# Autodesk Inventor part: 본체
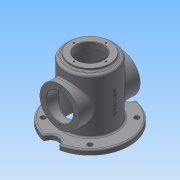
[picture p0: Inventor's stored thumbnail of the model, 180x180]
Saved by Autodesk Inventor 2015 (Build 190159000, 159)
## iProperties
Created: 2018-04
Part Number: 본체
Material: 일반
Document SubType Name: Modeling
Designer: user
Density: 1 g/cm^3
Appearance: 기본값
Mass: 425.882 g
Surface Area: 1203.14 cm^2
Volume: 425.882 cm^3
Author: user
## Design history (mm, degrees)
sketch "스케치2"
  geometry: C1 r 45 at (0, 0); C2 r 50 at (0, 0); 1 further point
  constraints: 2 centre point, 2 coincident
  dimensions: "d0" = 90 diameter of C1; "d1" = 100 diameter of C2
extrude "돌출1" new body sketch "스케치2" distance "d2" = 128; taper "d3" = 0 deg
node "작업 평면1"
sketch "스케치3"
  geometry: L1 (0, 0)-(0, 80); L2 (0, 0)-(0, -80); C1 r 45 at (0, 0); A1 r 15 centre (0, 80) between (-14.934, 78.594) and (14.934, 78.594); A2 r 15 centre (0, -80) between (14.934, -78.594) and (-14.934, -78.594); A3 r 80 centre (0, 0) between (-14.934, 78.594) and (-14.934, -78.594); A4 r 80 centre (0, 0) between (14.934, -78.594) and (14.934, 78.594); A5 r 67.5 centre (0, 0) between (-7.604, 67.07) and (-7.604, -67.07); A6 r 67.5 centre (0, 0) between (7.604, -67.07) and (7.604, 67.07); 1 further point
  constraints: 16 point on circle, 7 centre point, 5 coincident, 4 end point, 2 vertical
  dimensions: "d6" = 90 diameter of C1; "d10" = 30 diameter of A1; "d11" = 30 diameter of A2; "d12" = 80 distance of L1.start L1.end; "d13" = 80 distance of L1.start L2.end; "d14" = 80 radius of A3; "d15" = 67.5 radius of A5; "d16" = 67.5 radius of A6; "d17" = 80 radius of A4
extrude "돌출2" join sketch "스케치3" distance "d18" = 10; taper "d19" = 0 deg
sketch "스케치4"
  geometry: L1 (0, 0)-(-47.73, 47.73); L2 (0, 0)-(-47.73, -47.73); L3 (0, 0)-(0, -36.099); L4 (0, 0)-(47.73, 47.73); L5 (0, 0)-(47.73, -47.73); C1 r 50 at (0, 0) reference; A1 r 67.5 centre (0, 0) between (-47.73, 47.73) and (-47.73, -47.73); 4 further points
  constraints: 10 end point, 5 coincident, 2 point on circle, 2 symmetric about line, 1 centre point, 1 vertical
  dimensions: "d21" = 45 deg angle of L3 L2; "d22" = 90 deg angle of L1 L2; "d23" = 135 diameter of A1
hole "구멍1" sketch "스케치4" at (-47.73, -47.73), (-47.73, 47.73), (47.73, 47.73), (47.73, -47.73) diameter "d24" = 10; stored, may be unused: countersink angle "d28" = 90 deg, drill point angle "d30" = 118 deg; dims "d25" = 6, "d26" = 4, "d27" = 2, "d29" = 8
node "작업 평면2"
sketch "스케치6"
  geometry: C1 r 27 at (0, 0); C2 r 40 at (0, 0); 1 further point
  constraints: 2 centre point, 2 coincident
  dimensions: "d32" = 54 diameter of C1; "d33" = 80 diameter of C2
extrude "돌출3" join sketch "스케치6" distance "d34" = 5; taper "d35" = 0 deg
node "작업 평면3"
sketch "스케치7"
  geometry: C1 r 50 at (0, 0); 1 further point
  constraints: 1 centre point, 1 coincident
  dimensions: "d37" = 100 diameter of C1
extrude "돌출4" join sketch "스케치7" distance "d38" = 8; taper "d39" = 0 deg
extrude "돌출5" cut sketch "스케치6" stored distance "d40" = 8; taper "d41" = 0 deg
node "작업 평면4"
sketch "스케치10"
  geometry: L1 (0, 0)-(0, 68); C1 r 40 at (0, 68); C2 r 27 at (0, 68)
  constraints: 2 centre point, 2 coincident, 2 end point, 1 vertical
  dimensions: "d48" = 68 distance of L1.start L1.end; "d49" = 80 diameter of C1; "d50" = 54 diameter of C2
extrude "돌출6" join sketch "스케치10" stored distance "d51" = 8; taper "d52" = 0 deg
extrude "돌출7" cut sketch "스케치10" stored distance "d53" = 8; taper "d54" = 0 deg
sketch "스케치11"
  geometry: L1 (0, 0)-(0, -32.5); L2 (0, 0)-(32.5, 0); L3 (0, 0)-(-32.5, 0); L4 (0, 0)-(0, 32.5); C1 r 40 at (0, 0) reference; A1 r 32.5 centre (0, 0) between (0, -32.5) and (32.5, 0); 4 further points
  constraints: 8 end point, 5 coincident, 4 point on circle, 2 horizontal, 2 vertical, 1 centre point
  dimensions: "d55" = 65 diameter of A1
hole "구멍2" sketch "스케치11" at (0, -32.5), (-32.5, 0), (0, 32.5), (32.5, 0) diameter "d56" = 3.242; stored, may be unused: countersink angle "d60" = 90 deg, drill point angle "d62" = 118 deg; dims "d57" = 8, "d58" = 4, "d59" = 2, "d61" = 10
sketch "스케치12"
  geometry: L1 (0, 0)-(0, 32.5); L2 (0, 0)-(32.5, 0); L3 (0, 0)-(0, -32.5); L4 (0, 0)-(-32.5, 0); C1 r 40 at (0, 0) reference; A1 r 32.5 centre (0, 0) between (0, 32.5) and (32.5, 0); 5 further points
  constraints: 8 end point, 5 coincident, 4 point on circle, 2 horizontal, 2 vertical, 1 centre point
  dimensions: "d63" = 65 diameter of A1
hole "구멍3" sketch "스케치12" at (0, 32.5), (32.5, 0), (0, -32.5), (-32.5, 0) diameter "d64" = 3.242; stored, may be unused: countersink angle "d68" = 90 deg, drill point angle "d70" = 118 deg; dims "d65" = 8, "d66" = 4, "d67" = 2, "d69" = 10
chamfer "모따기1" distance "d71" = 1; stored, may be unused: second distance "d72" = 2, angle "d73" = 45 deg
fillet "모깎기1" dims "d26" = 4, "d74" = 3, "d79" = 5
fillet "모깎기2" dims "d75" = 3
node "작업 평면5"
sketch "스케치13"
  geometry: 2 further points
  constraints: 1 horizontal alignment, 1 other
  dimensions: "d76" = 70 distance of point (0, 0) point (70, 0)
feature "엠보싱1" sketch "스케치13" dims "d77" = 0.5, "d78" = 0
node "솔리드1"
mirror "대칭1"
mirror "대칭2"
other parameters: "d4" = -8, "d7" = 135, "d31" = -133, "d36" = 5, "d47" = 62
